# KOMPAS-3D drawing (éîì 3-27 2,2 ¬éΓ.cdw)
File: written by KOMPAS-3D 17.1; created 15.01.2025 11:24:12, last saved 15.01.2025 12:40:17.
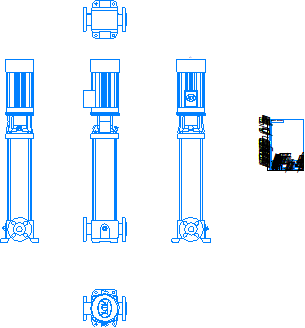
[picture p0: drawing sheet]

Sheet 1: A4, portrait

Title block, sheet 1: name: ВМН 3-27 2,2 кВт; designation: ВМН 3-27 2,2 кВт; material: Сталь 10  ГОСТ 1050-2013; mass: 0,03; sheets: 1; sheet format: A4; stored path: \\adlc.lan\data\АДЛ_ПКД\3D-модели\ADL production\Насосы ГРАНПАМП\Насосы ВМН\ВМН3\KOMPAS 3D\ВМН 3-27 2,2 кВт.cdw

Views: Проекционный вид 2, Проекционный вид 3, Проекционный вид 4, Проекционный вид 5
Referenced files in \\adlc.lan\data\АДЛ_ПКД\3D-модели\ADL production\Насосы ГРАНПАМП\Насосы ВМН\ВМН3\KOMPAS 3D\: ВМН 3-27 2,2 кВт.m3d
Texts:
  Andrey
  АДЛ
Dimensions and other numbers on the sheet: 1:1; 1; 0,03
